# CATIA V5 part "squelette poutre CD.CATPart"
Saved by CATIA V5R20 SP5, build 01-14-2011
Part number: squelette poutre CD
Publications: "Droite.1", "Point.2", "Point.1"
Bounding box of the stored display mesh (mm): x 0 to 200, y 25.674 to 2799.537, z -86.054 to 1485.26
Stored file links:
  F:\iao fini\squelette poutre CD.CATPart
  F:\iao fini\iao-finipbgliss.CATProduct
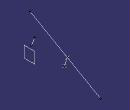
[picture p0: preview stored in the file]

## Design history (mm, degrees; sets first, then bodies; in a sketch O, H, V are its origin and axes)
Set1
  Line1: linked copy from another document
  Line2: linked copy from another document
Body1 (main body)
  Set2
    Plane1 "Plan CD": type Offset, RefPlane yz-plane, Offset 0
    Point1: type OnPlane, Support Plane1, H 1375.213, V 310.49, Direction (0, 1, 0)
    Line3: type PtDir, LineSecondUpto Line2, RefPoint Point1, Direction Line1, Start 0, End 20
    Point2: type OnPlane, Support Plane1, H 1500.1993, V 649.9838, Direction (0, 1, 0)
